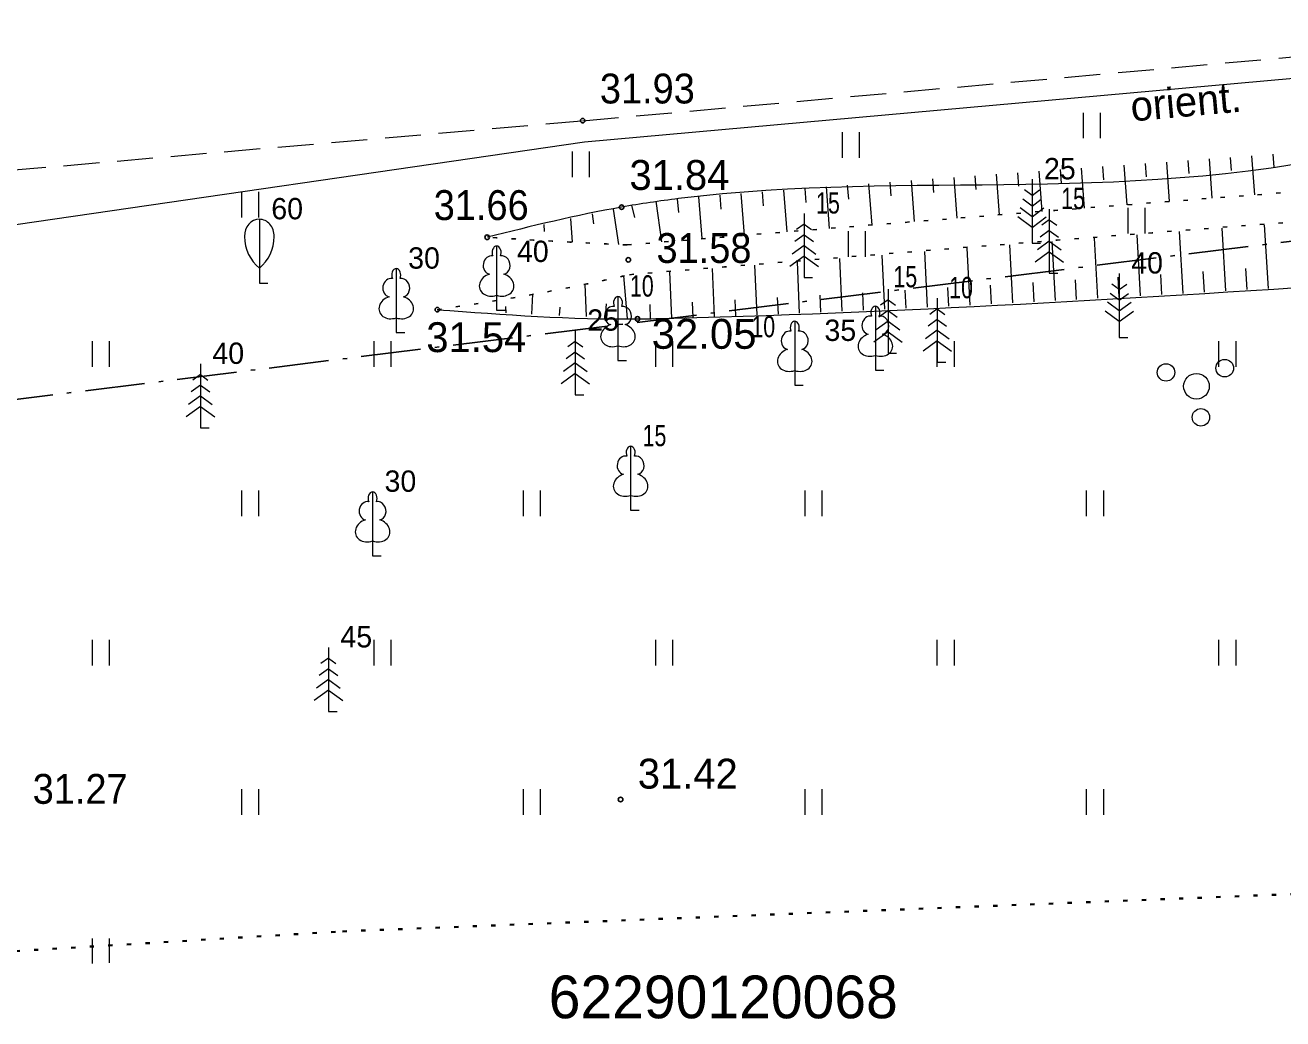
# Model space of a CAD drawing. Extents: x 380758 to 381729, y 283236 to 283533.
# Drawn here: x 380991.59 to 381021.07, y 283306.6 to 283329.89 of the extents above; entities that cross this region are included whole.
import ezdxf
from ezdxf.enums import TextEntityAlignment as Align

# ---------------------------------------------------------------- set-up
doc = ezdxf.new("R2010")
doc.units = 0
doc.header["$LTSCALE"] = 0.28
for name, pattern in [('DOT_DASHED', [7.7, 5, -1.2, 0.3, -1.2]), ('DOTTED', [1.5, 0.3, -1.2]), ('MEDIUM_DASHED', [4.5, 3, -1.5])]:
    doc.linetypes.add(name, pattern=pattern)
for name, color, linetype, lineweight in [('1', 7, 'Continuous', 13), ('17', 7, 'Continuous', 13), ('23', 7, 'Continuous', 13), ('25', 7, 'DOTTED', 35), ('29', 7, 'DOT_DASHED', 25), ('31', 7, 'Continuous', 13), ('37', 7, 'MEDIUM_DASHED', 13), ('58', 7, 'Continuous', 25)]:
    doc.layers.add(name, color=color, linetype=linetype, lineweight=lineweight)
doc.layers.add('59', color=7, linetype='Continuous')

msp = doc.modelspace()

# ---------------------------------------------------------------- linework, layer by layer
at = {"layer": '1'}
for p, q in [((381015.193, 283326.274), (381015.193, 283324.774)), ((381015.193, 283325.898), (381015.017, 283326.026)), ((381015.193, 283325.898), (381015.367, 283326.026)), ((381015.193, 283325.398), (381014.915, 283325.602)), ((381015.193, 283325.648), (381014.977, 283325.806)), ((381015.193, 283325.648), (381015.409, 283325.806)), ((381015.193, 283325.398), (381015.471, 283325.602)), ((381015.596, 283325.575), (381015.596, 283324.075)), ((380997.083, 283325.337), (380997.083, 283324.189)), ((381009.851, 283325.472), (381009.851, 283323.972)), ((381015.193, 283325.148), (381014.861, 283325.392)), ((381015.193, 283325.148), (381015.527, 283325.392)), ((381015.596, 283325.325), (381015.42, 283325.197)), ((381015.596, 283325.325), (381015.77, 283325.197)), ((381009.851, 283324.972), (381009.635, 283324.814)), ((381009.851, 283325.222), (381009.675, 283325.094)), ((381009.851, 283325.222), (381010.025, 283325.094)), ((381009.851, 283324.972), (381010.067, 283324.814)), ((381015.596, 283325.075), (381015.38, 283324.917)), ((381015.596, 283325.075), (381015.812, 283324.917)), ((381002.644, 283324.71), (381002.644, 283323.557)), ((381009.851, 283324.722), (381009.573, 283324.518)), ((381009.851, 283324.722), (381010.129, 283324.518)), ((381015.193, 283324.774), (381015.393, 283324.774)), ((381015.596, 283324.825), (381015.318, 283324.621)), ((381015.596, 283324.825), (381015.874, 283324.621)), ((381002.734, 283324.478), (381002.733, 283324.479)), ((381009.851, 283324.472), (381009.519, 283324.228)), ((381009.851, 283324.472), (381010.185, 283324.228)), ((381015.596, 283324.575), (381015.264, 283324.331)), ((381015.596, 283324.575), (381015.93, 283324.331)), ((380997.083, 283324.189), (380997.083, 283323.837)), ((381000.291, 283324.18), (381000.291, 283323.027)), ((381015.596, 283324.075), (381015.796, 283324.075)), ((381017.237, 283324.066), (381017.237, 283322.566)), ((380997.083, 283323.837), (380997.283, 283323.837)), ((381000.381, 283323.948), (381000.38, 283323.949)), ((381009.851, 283323.972), (381010.051, 283323.972)), ((381017.237, 283323.69), (381017.061, 283323.818)), ((381017.237, 283323.69), (381017.411, 283323.818)), ((381002.644, 283323.557), (381002.644, 283323.21)), ((381005.488, 283323.525), (381005.488, 283322.372)), ((381011.817, 283323.701), (381011.817, 283322.201)), ((381012.971, 283323.487), (381012.971, 283321.987)), ((381017.237, 283323.44), (381017.021, 283323.598)), ((381017.237, 283323.44), (381017.453, 283323.598)), ((381002.644, 283323.21), (381002.844, 283323.21)), ((381005.578, 283323.293), (381005.577, 283323.294)), ((381011.521, 283323.3), (381011.521, 283322.147)), ((381011.817, 283323.201), (381011.601, 283323.043)), ((381011.817, 283323.451), (381011.641, 283323.323)), ((381011.817, 283323.451), (381011.991, 283323.323)), ((381011.817, 283323.201), (381012.033, 283323.043)), ((381012.971, 283323.237), (381012.795, 283323.109)), ((381012.971, 283323.237), (381013.145, 283323.109)), ((381017.237, 283322.94), (381016.905, 283323.184)), ((381017.237, 283323.19), (381016.959, 283323.394)), ((381017.237, 283323.19), (381017.515, 283323.394)), ((381017.237, 283322.94), (381017.571, 283323.184)), ((381000.291, 283323.027), (381000.291, 283322.68)), ((381009.631, 283322.946), (381009.631, 283321.793)), ((381011.817, 283322.951), (381011.539, 283322.747)), ((381011.611, 283323.068), (381011.61, 283323.069)), ((381011.817, 283322.951), (381012.095, 283322.747)), ((381012.971, 283322.987), (381012.755, 283322.829)), ((381012.971, 283322.987), (381013.187, 283322.829)), ((381000.291, 283322.68), (381000.491, 283322.68)), ((381004.487, 283322.726), (381004.487, 283321.226)), ((381009.721, 283322.714), (381009.72, 283322.715)), ((381011.817, 283322.701), (381011.485, 283322.457)), ((381011.817, 283322.701), (381012.151, 283322.457)), ((381012.971, 283322.737), (381012.693, 283322.533)), ((381012.971, 283322.737), (381013.249, 283322.533)), ((381004.487, 283322.476), (381004.311, 283322.348)), ((381004.487, 283322.476), (381004.661, 283322.348)), ((381005.488, 283322.372), (381005.488, 283322.025)), ((381012.971, 283322.487), (381012.639, 283322.243)), ((381012.971, 283322.487), (381013.305, 283322.243)), ((381017.237, 283322.566), (381017.437, 283322.566)), ((381004.487, 283322.226), (381004.271, 283322.068)), ((381004.487, 283322.226), (381004.703, 283322.068)), ((381005.488, 283322.025), (381005.688, 283322.025)), ((381011.521, 283322.147), (381011.521, 283321.8)), ((381011.817, 283322.201), (381012.017, 283322.201)), ((380995.703, 283321.698), (380995.527, 283321.57)), ((380995.703, 283321.948), (380995.703, 283320.448)), ((380995.703, 283321.698), (380995.877, 283321.57)), ((381004.487, 283321.726), (381004.155, 283321.482)), ((381004.487, 283321.976), (381004.209, 283321.772)), ((381004.487, 283321.976), (381004.765, 283321.772)), ((381004.487, 283321.726), (381004.821, 283321.482)), ((381009.631, 283321.793), (381009.631, 283321.446)), ((381011.521, 283321.8), (381011.721, 283321.8)), ((381012.971, 283321.987), (381013.171, 283321.987)), ((380995.703, 283321.448), (380995.487, 283321.29)), ((380995.703, 283321.448), (380995.919, 283321.29)), ((381009.631, 283321.446), (381009.831, 283321.446)), ((380995.703, 283321.198), (380995.425, 283320.994)), ((380995.703, 283321.198), (380995.981, 283320.994)), ((381004.487, 283321.226), (381004.687, 283321.226)), ((380995.703, 283320.948), (380995.371, 283320.704)), ((380995.703, 283320.948), (380996.037, 283320.704)), ((380995.703, 283320.448), (380995.903, 283320.448)), ((381005.785, 283320.019), (381005.785, 283318.866)), ((381005.875, 283319.787), (381005.874, 283319.788)), ((380999.737, 283318.95), (380999.737, 283317.797)), ((381005.785, 283318.866), (381005.785, 283318.519)), ((380999.827, 283318.718), (380999.826, 283318.719)), ((381005.785, 283318.519), (381005.985, 283318.519)), ((380999.737, 283317.797), (380999.737, 283317.45)), ((380999.737, 283317.45), (380999.937, 283317.45)), ((380998.703, 283315.303), (380998.703, 283313.803)), ((380998.703, 283315.053), (380998.527, 283314.925)), ((380998.703, 283315.053), (380998.877, 283314.925)), ((380998.703, 283314.803), (380998.487, 283314.645)), ((380998.703, 283314.803), (380998.919, 283314.645)), ((380998.703, 283314.553), (380998.425, 283314.349)), ((380998.703, 283314.553), (380998.981, 283314.349)), ((380998.703, 283314.303), (380998.371, 283314.059)), ((380998.703, 283314.303), (380999.037, 283314.059)), ((380998.703, 283313.803), (380998.903, 283313.803))]:
    msp.add_line(p, q, dxfattribs=at)
for centre, radius in [((381019.7084, 283321.8482), 0.2066), ((381018.3328, 283321.7472), 0.2041), ((381019.0469, 283321.4233), 0.3006), ((381019.1502, 283320.6958), 0.2045)]:
    msp.add_circle(centre, radius, dxfattribs=at)
for centre, major_axis, ratio, start_param, end_param in [((380997.083, 283324.937), (0, 0.4), 0.875, 0, 1.5707963), ((380997.083, 283324.937), (0, -0.4), 0.875, 1.5707963, 3.1415927), ((380997.083, 283324.937), (0, -0.4), 0.875, 1.5707963, 3.1415927), ((380997.5583, 283324.9604), (0, -0.9434), 0.875, 4.7372004, 5.6697113), ((380996.6077, 283324.9604), (0, -0.9434), 0.875, 0.613474, 1.5459849), ((381002.6444, 283324.5601), (0, -0.1499), 0.707107, 3.1453698, 5.2874846), ((381002.6436, 283324.5601), (0, -0.1499), 0.707107, 0.9957007, 3.1378155), ((381002.5157, 283324.2652), (-0.0387, -0.2124), 0.861323, 3.1415927, 6.2831853), ((381002.7723, 283324.2652), (0.0387, -0.2124), 0.861323, 6.2831853, 9.424778), ((381000.2914, 283324.0301), (0, -0.1499), 0.707107, 3.1453698, 5.2874846), ((381000.2906, 283324.0301), (0, -0.1499), 0.707107, 0.9957007, 3.1378155), ((381000.1627, 283323.7352), (-0.0387, -0.2124), 0.861323, 3.1415927, 6.2831853), ((381000.4193, 283323.7352), (0.0387, -0.2124), 0.861323, 6.2831853, 9.424778), ((381002.5544, 283323.8029), (0.3068, 0.0951), 0.814445, 1.5707963, 4.7520146), ((381002.7336, 283323.8029), (-0.3068, 0.0951), 0.814445, 1.5311707, 4.712389), ((381000.2014, 283323.2729), (0.3068, 0.0951), 0.814445, 1.5707963, 4.7520146), ((381000.3806, 283323.2729), (-0.3068, 0.0951), 0.814445, 1.5311707, 4.712389), ((381005.4884, 283323.3751), (0, -0.1499), 0.707107, 3.1453698, 5.2874846), ((381005.4876, 283323.3751), (0, -0.1499), 0.707107, 0.9957007, 3.1378155), ((381005.3597, 283323.0802), (-0.0387, -0.2124), 0.861323, 3.1415927, 6.2831853), ((381005.6163, 283323.0802), (0.0387, -0.2124), 0.861323, 6.2831853, 9.424778), ((381011.5214, 283323.1501), (0, -0.1499), 0.707107, 3.1453698, 5.2874846), ((381011.5206, 283323.1501), (0, -0.1499), 0.707107, 0.9957007, 3.1378155), ((381009.6314, 283322.7961), (0, -0.1499), 0.707107, 3.1453698, 5.2874846), ((381009.6306, 283322.7961), (0, -0.1499), 0.707107, 0.9957007, 3.1378155), ((381011.3927, 283322.8552), (-0.0387, -0.2124), 0.861323, 3.1415927, 6.2831853), ((381011.6493, 283322.8552), (0.0387, -0.2124), 0.861323, 6.2831853, 9.424778), ((381005.3984, 283322.6179), (0.3068, 0.0951), 0.814445, 1.5707963, 4.7520146), ((381005.5776, 283322.6179), (-0.3068, 0.0951), 0.814445, 1.5311707, 4.712389), ((381009.5027, 283322.5012), (-0.0387, -0.2124), 0.861323, 3.1415927, 6.2831853), ((381009.7593, 283322.5012), (0.0387, -0.2124), 0.861323, 6.2831853, 9.424778), ((381011.4314, 283322.3929), (0.3068, 0.0951), 0.814445, 1.5707963, 4.7520146), ((381011.6106, 283322.3929), (-0.3068, 0.0951), 0.814445, 1.5311707, 4.712389), ((381009.5414, 283322.0389), (0.3068, 0.0951), 0.814445, 1.5707963, 4.7520146), ((381009.7206, 283322.0389), (-0.3068, 0.0951), 0.814445, 1.5311707, 4.712389), ((381005.7854, 283319.8691), (0, -0.1499), 0.707107, 3.1453698, 5.2874846), ((381005.7846, 283319.8691), (0, -0.1499), 0.707107, 0.9957007, 3.1378155), ((381005.6567, 283319.5742), (-0.0387, -0.2124), 0.861323, 3.1415927, 6.2831853), ((381005.9133, 283319.5742), (0.0387, -0.2124), 0.861323, 6.2831853, 9.424778), ((381005.6954, 283319.1119), (0.3068, 0.0951), 0.814445, 1.5707963, 4.7520146), ((381005.8746, 283319.1119), (-0.3068, 0.0951), 0.814445, 1.5311707, 4.712389), ((380999.7374, 283318.8001), (0, -0.1499), 0.707107, 3.1453698, 5.2874846), ((380999.7366, 283318.8001), (0, -0.1499), 0.707107, 0.9957007, 3.1378155), ((380999.6087, 283318.5052), (-0.0387, -0.2124), 0.861323, 3.1415927, 6.2831853), ((380999.8653, 283318.5052), (0.0387, -0.2124), 0.861323, 6.2831853, 9.424778), ((380999.6474, 283318.0429), (0.3068, 0.0951), 0.814445, 1.5707963, 4.7520146), ((380999.8266, 283318.0429), (-0.3068, 0.0951), 0.814445, 1.5311707, 4.712389)]:
    msp.add_ellipse(centre, major_axis=major_axis, ratio=ratio, start_param=start_param, end_param=end_param, dxfattribs=at)
at = {"layer": '17'}
msp.add_line((380978.857, 283323.404), (381004.704, 283327.15), dxfattribs=at)
msp.add_lwpolyline([(381004.704, 283327.15), (381023.231, 283328.814), (381038.659, 283329.771)], dxfattribs=at)
at = {"layer": '23'}
for p, q in [((381016.399, 283327.235), (381016.399, 283327.835)), ((381016.799, 283327.235), (381016.799, 283327.835)), ((381010.751, 283326.78), (381010.751, 283327.38)), ((381011.151, 283326.78), (381011.151, 283327.38)), ((381004.421, 283326.324), (381004.421, 283326.924)), ((381004.821, 283326.324), (381004.821, 283326.924)), ((380996.673, 283325.38), (380996.673, 283325.98)), ((380997.073, 283325.38), (380997.073, 283325.98)), ((381017.446, 283325.002), (381017.446, 283325.602)), ((381017.846, 283325.002), (381017.846, 283325.602)), ((381010.888, 283324.455), (381010.888, 283325.055)), ((381011.288, 283324.455), (381011.288, 283325.055)), ((380993.173, 283321.88), (380993.173, 283322.48)), ((380993.573, 283321.88), (380993.573, 283322.48)), ((380999.773, 283321.88), (380999.773, 283322.48)), ((381000.173, 283321.88), (381000.173, 283322.48)), ((381006.373, 283321.88), (381006.373, 283322.48)), ((381006.773, 283321.88), (381006.773, 283322.48)), ((381012.973, 283321.88), (381012.973, 283322.48)), ((381013.373, 283321.88), (381013.373, 283322.48)), ((381019.573, 283321.88), (381019.573, 283322.48)), ((381019.973, 283321.88), (381019.973, 283322.48)), ((380996.673, 283318.38), (380996.673, 283318.98)), ((380997.073, 283318.38), (380997.073, 283318.98)), ((381003.273, 283318.38), (381003.273, 283318.98)), ((381003.673, 283318.38), (381003.673, 283318.98)), ((381009.873, 283318.38), (381009.873, 283318.98)), ((381010.273, 283318.38), (381010.273, 283318.98)), ((381016.473, 283318.38), (381016.473, 283318.98)), ((381016.873, 283318.38), (381016.873, 283318.98)), ((380993.173, 283314.88), (380993.173, 283315.48)), ((380993.573, 283314.88), (380993.573, 283315.48)), ((380999.773, 283314.88), (380999.773, 283315.48)), ((381000.173, 283314.88), (381000.173, 283315.48)), ((381006.373, 283314.88), (381006.373, 283315.48)), ((381006.773, 283314.88), (381006.773, 283315.48)), ((381012.973, 283314.88), (381012.973, 283315.48)), ((381013.373, 283314.88), (381013.373, 283315.48)), ((381019.573, 283314.88), (381019.573, 283315.48)), ((381019.973, 283314.88), (381019.973, 283315.48)), ((380996.673, 283311.38), (380996.673, 283311.98)), ((380997.073, 283311.38), (380997.073, 283311.98)), ((381003.273, 283311.38), (381003.273, 283311.98)), ((381003.673, 283311.38), (381003.673, 283311.98)), ((381009.873, 283311.38), (381009.873, 283311.98)), ((381010.273, 283311.38), (381010.273, 283311.98)), ((381016.473, 283311.38), (381016.473, 283311.98)), ((381016.873, 283311.38), (381016.873, 283311.98)), ((380993.173, 283307.894), (380993.173, 283308.48)), ((380993.573, 283307.907), (380993.573, 283308.48))]:
    msp.add_line(p, q, dxfattribs=at)
at = {"layer": '25'}
msp.add_lwpolyline([(380965.254, 283306.611), (380999.033, 283308.647), (381050.794, 283310.677), (381081.859, 283313.257), (381112.788, 283315.836), (381135.685, 283318.987), (381169.311, 283321.878), (381185.52, 283321.507), (381211.031, 283321.569), (381227.246, 283323.167), (381243.045, 283326.858), (381256.971, 283328.14), (381276.827, 283329.124), (381289.49, 283330.785), (381296.806, 283333.369), (381324.562, 283332.372), (381358.23, 283334.462), (381389.309, 283326.777)], dxfattribs=at)
at = {"layer": '29'}
msp.add_line((380977.917, 283319.444), (381029.754, 283325.877), dxfattribs=at)
at = {"layer": '31'}
for p, q in [((381018.842, 283326.715), (381018.864, 283326.408)), ((381019.341, 283326.751), (381019.407, 283325.834)), ((381019.839, 283326.787), (381019.862, 283326.482)), ((381020.338, 283326.823), (381020.404, 283325.912)), ((381020.837, 283326.86), (381020.859, 283326.556)), ((381014.852, 283326.429), (381014.875, 283326.111)), ((381015.351, 283326.465), (381015.419, 283325.52)), ((381015.85, 283326.501), (381015.872, 283326.186)), ((381016.348, 283326.537), (381016.416, 283325.599)), ((381016.847, 283326.572), (381016.87, 283326.26)), ((381017.346, 283326.608), (381017.413, 283325.678)), ((381017.845, 283326.644), (381017.867, 283326.334)), ((381018.343, 283326.68), (381018.41, 283325.756)), ((381010.863, 283326.134), (381010.888, 283325.81)), ((381011.362, 283326.172), (381011.435, 283325.202)), ((381011.86, 283326.209), (381011.885, 283325.886)), ((381012.359, 283326.246), (381012.431, 283325.282)), ((381012.858, 283326.283), (381012.881, 283325.962)), ((381013.356, 283326.32), (381013.427, 283325.361)), ((381013.855, 283326.356), (381013.878, 283326.037)), ((381014.354, 283326.393), (381014.423, 283325.441)), ((381007.374, 283325.86), (381007.453, 283324.885)), ((381007.872, 283325.9), (381007.898, 283325.575)), ((381008.371, 283325.94), (381008.448, 283324.964)), ((381008.869, 283325.98), (381008.895, 283325.654)), ((381009.368, 283326.019), (381009.444, 283325.044)), ((381009.866, 283326.057), (381009.891, 283325.732)), ((381010.365, 283326.096), (381010.439, 283325.123)), ((381005.376, 283325.578), (381005.5, 283324.747)), ((381005.809, 283325.671), (381005.877, 283325.378)), ((381006.379, 283325.765), (381006.506, 283324.81)), ((381006.876, 283325.819), (381006.903, 283325.499)), ((381004.372, 283325.353), (381004.416, 283324.8)), ((381004.883, 283325.467), (381004.917, 283325.229)), ((381003.749, 283325.213), (381003.757, 283325.054)), ((381017.736, 283323.543), (381017.655, 283324.975)), ((381018.734, 283323.6), (381018.651, 283325.053)), ((381019.732, 283323.658), (381019.646, 283325.131)), ((381020.731, 283323.717), (381020.642, 283325.208)), ((381013.742, 283323.328), (381013.674, 283324.659)), ((381014.74, 283323.38), (381014.669, 283324.738)), ((381015.739, 283323.433), (381015.664, 283324.817)), ((381016.737, 283323.488), (381016.659, 283324.896)), ((381010.745, 283323.183), (381010.689, 283324.421)), ((381011.744, 283323.229), (381011.684, 283324.5)), ((381012.743, 283323.278), (381012.679, 283324.579)), ((381006.749, 283323.017), (381006.705, 283324.104)), ((381007.748, 283323.055), (381007.704, 283324.183)), ((381008.747, 283323.096), (381008.699, 283324.262)), ((381009.746, 283323.138), (381009.694, 283324.341)), ((381019.233, 283323.629), (381019.205, 283324.11)), ((381020.232, 283323.688), (381020.202, 283324.185)), ((381004.751, 283323.057), (381004.723, 283323.813)), ((381005.714, 283323.013), (381005.626, 283324.011)), ((381014.241, 283323.354), (381014.218, 283323.795)), ((381015.24, 283323.406), (381015.216, 283323.857)), ((381016.238, 283323.46), (381016.213, 283323.919)), ((381017.237, 283323.515), (381017.21, 283323.982)), ((381018.235, 283323.572), (381018.208, 283324.046)), ((381003.469, 283323.116), (381003.492, 283323.585)), ((381009.247, 283323.117), (381009.23, 283323.505)), ((381010.246, 283323.16), (381010.228, 283323.56)), ((381011.245, 283323.206), (381011.225, 283323.617)), ((381012.243, 283323.253), (381012.223, 283323.675)), ((381013.242, 283323.303), (381013.221, 283323.735)), ((381002.87, 283323.144), (381002.859, 283323.294)), ((381004.118, 283323.086), (381004.131, 283323.281)), ((381005.199, 283323.036), (381005.216, 283323.356)), ((381006.249, 283322.999), (381006.243, 283323.343)), ((381007.248, 283323.036), (381007.234, 283323.398)), ((381008.247, 283323.075), (381008.232, 283323.451))]:
    msp.add_line(p, q, dxfattribs=at)
for points in [[(381039.182, 283327.165), (381038.146, 283328.274), (381023.538, 283327.059), (381006.908, 283325.821), (381005.574, 283325.622), (381002.421, 283324.916)], [(381001.254, 283323.218), (381005.947, 283323.002), (381006.798, 283323.019), (381024.075, 283323.919), (381037.325, 283325.402), (381038.183, 283325.66), (381039.182, 283327.165)]]:
    msp.add_spline(points, degree=3, dxfattribs=at)
at = {"layer": '31', "linetype": 'DOTTED', "lineweight": 25}
for points in [[(381005.703, 283324.737), (381023.525, 283326.141), (381037.872, 283327.131)], [(381005.757, 283324.039), (381023.577, 283325.443), (381037.92, 283326.433)], [(381005.703, 283324.737), (381004.167, 283324.813), (381002.421, 283324.916)], [(381001.254, 283323.218), (381004.425, 283323.753), (381005.757, 283324.039)]]:
    msp.add_spline(points, degree=3, dxfattribs=at)
at = {"layer": '37'}
msp.add_lwpolyline([(380960.031, 283321.322), (380961.395, 283323.927), (380978.688, 283325.397), (381004.66, 283327.648), (381023.193, 283329.313), (381038.628, 283330.27), (381040.257, 283328.298), (381040.427, 283322.787)], dxfattribs=at)
at = {"layer": '58'}
for centre in [(381004.66, 283327.6481), (381005.574, 283325.6221), (381002.421, 283324.9161), (381005.73, 283324.3881), (381001.254, 283323.2181), (381005.947, 283323.0021), (381005.549, 283311.7371)]:
    msp.add_circle(centre, 0.0534, dxfattribs=at)

# ---------------------------------------------------------------- texts
at = {"layer": '1'}
for s, p in [('25', (381015.473, 283326.274)), ('60', (380997.363, 283325.337)), ('30', (381000.571, 283324.18)), ('40', (381003.121, 283324.336)), ('40', (381017.517, 283324.066)), ('25', (381004.767, 283322.726)), ('35', (381010.328, 283322.486)), ('40', (380995.983, 283321.948)), ('30', (381000.017, 283318.95)), ('45', (380998.983, 283315.303))]:
    msp.add_text(s, height=0.5, dxfattribs=at).set_placement(p)
at = {"layer": '1', "width": 0.75}
for s, p in [('15', (381010.131, 283325.472)), ('15', (381015.876, 283325.575)), ('15', (381011.943, 283323.744)), ('10', (381005.768, 283323.525)), ('10', (381013.251, 283323.487)), ('10', (381008.614, 283322.572)), ('15', (381006.065, 283320.019))]:
    msp.add_text(s, height=0.5, dxfattribs=at).set_placement(p)
at = {"layer": '17'}
msp.add_text('orient.', height=0.7, rotation=5.134, dxfattribs=at).set_placement((381018.8277, 283327.7459), align=Align.CENTER)
at = {"layer": '58'}
for s, width, p in [('31.93', 0.95, (381005.064, 283328.052)), ('31.66', 0.95, (381001.17, 283325.32)), ('31.58', 0.95, (381006.391, 283324.314)), ('32.05', 1.05, (381006.277, 283322.302)), ('31.27', 0.95, (380991.771, 283311.637))]:
    msp.add_text(s, height=0.7, dxfattribs=dict(at, width=width)).set_placement(p)
for s, p in [('31.84', (381005.757, 283326.026)), ('31.54', (381000.996, 283322.224)), ('31.42', (381005.953, 283311.994))]:
    msp.add_text(s, height=0.7, dxfattribs=at).set_placement(p)
at = {"layer": '59'}
msp.add_text('62290120068', height=1, dxfattribs=at).set_placement((381003.865, 283306.611))

doc.saveas('drawing.dxf')
